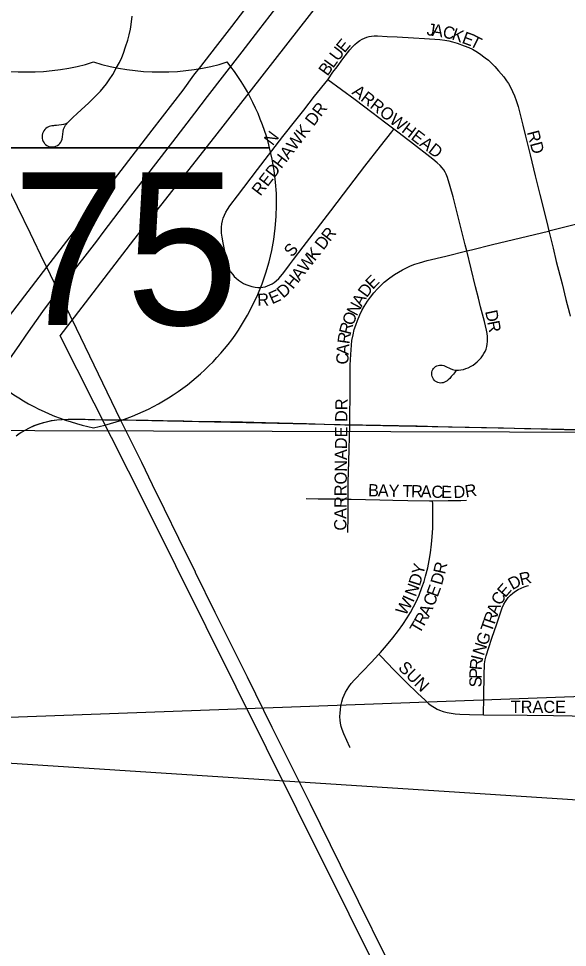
# Model space of a CAD drawing. Extents: x -5.6 to 34, y 0 to 22.
# Drawn here: x 6.458 to 7.358, y 18.084 to 19.608 of the extents above; entities that cross this region are included whole.
import ezdxf

# ---------------------------------------------------------------- set-up
doc = ezdxf.new("R2010")
doc.units = 0
for name, color, linetype in [('GM_X_City_Street', 7, 'Continuous'), ('GM_X_City_Street_Text', 7, 'Continuous'), ('GM_X_Corporation', 7, 'Continuous'), ('GM_X_Interstate_Location', 7, 'Continuous'), ('GM_X_Interstate_Route', 7, 'Continuous'), ('GM_X_Interstate_Shield', 7, 'Continuous'), ('GM_X_Minor_River', 7, 'Continuous'), ('GM_X_Section', 7, 'Continuous'), ('GM_X_State_Route', 7, 'Continuous'), ('GM_X_Township_Road', 7, 'Continuous'), ('GM_X_Township_Subdivision', 7, 'Continuous'), ('GM_X_Township_Subdivision_Text', 7, 'Continuous'), ('SH_Text', 7, 'Continuous')]:
    doc.layers.add(name, color=color, linetype=linetype)

msp = doc.modelspace()

# ---------------------------------------------------------------- linework, layer by layer
at = {"layer": 'GM_X_City_Street'}
for points in [[(6.5359, 19.435), (6.5318, 19.4342), (6.5289, 19.4336), (6.5242, 19.4328), (6.5205, 19.4323), (6.5174, 19.4322), (6.5153, 19.432), (6.5131, 19.4317), (6.5108, 19.4313), (6.5084, 19.4306), (6.5061, 19.4295), (6.505, 19.4289), (6.503, 19.4274), (6.5021, 19.4265), (6.5013, 19.4256), (6.4996, 19.4237), (6.4984, 19.4214), (6.4975, 19.419), (6.497, 19.4164), (6.4968, 19.4138), (6.4971, 19.4112), (6.4978, 19.4087), (6.4987, 19.4062), (6.5, 19.4039), (6.5007, 19.4029), (6.5025, 19.401), (6.5046, 19.3994), (6.5069, 19.3982), (6.5094, 19.3975), (6.512, 19.3971), (6.5146, 19.3971), (6.5172, 19.3976), (6.5196, 19.3984), (6.522, 19.3996), (6.5241, 19.4012), (6.526, 19.403), (6.5276, 19.4051), (6.5288, 19.4074), (6.5297, 19.4098), (6.5305, 19.4137), (6.5313, 19.4228), (6.5315, 19.4241), (6.5317, 19.4254), (6.5321, 19.4265), (6.5335, 19.4297), (6.5341, 19.4308), (6.5354, 19.4329), (6.5361, 19.434), (6.5386, 19.437), (6.5422, 19.4408), (6.5479, 19.4462), (6.5538, 19.4514), (6.5616, 19.4584), (6.573, 19.4692), (6.5852, 19.4812), (6.5924, 19.4888), (6.5976, 19.4947), (6.6025, 19.5009), (6.607, 19.5073), (6.6126, 19.5162), (6.6185, 19.5264), (6.6235, 19.5357), (6.6274, 19.544), (6.6304, 19.5513), (6.6338, 19.5612), (6.6373, 19.5724), (6.6398, 19.5813), (6.6417, 19.5902), (6.6431, 19.598), (6.6448, 19.612)], [(6.9652, 19.5074), (6.9737, 19.5199), (6.9804, 19.5289), (6.9898, 19.5417), (7.0012, 19.5564), (7.0056, 19.5615), (7.0094, 19.5653), (7.0136, 19.5687), (7.018, 19.5718), (7.0215, 19.5739), (7.0252, 19.5758), (7.029, 19.5773), (7.033, 19.5784), (7.0371, 19.5791), (7.0412, 19.5795), (7.0466, 19.5795), (7.0624, 19.5785), (7.0787, 19.5777), (7.1056, 19.5763), (7.124, 19.5752), (7.1489, 19.5733), (7.1569, 19.5723), (7.1634, 19.5711), (7.1699, 19.5695), (7.1775, 19.5672), (7.1887, 19.5632), (7.1962, 19.5602), (7.2022, 19.5574), (7.2081, 19.5541), (7.2137, 19.5505), (7.2234, 19.5436), (7.2286, 19.5394), (7.2335, 19.5349), (7.2391, 19.5292), (7.2453, 19.5222), (7.2536, 19.512), (7.2584, 19.5056), (7.2614, 19.5012), (7.2647, 19.4953), (7.2683, 19.4882), (7.2715, 19.4809), (7.2743, 19.4734), (7.2774, 19.4633), (7.2807, 19.4505), (7.2851, 19.4327), (7.2896, 19.4148), (7.297, 19.3842), (7.3052, 19.3497), (7.3126, 19.3191), (7.32, 19.2912), (7.3259, 19.2669), (7.3277, 19.2594)], [(6.8057, 19.1923), (6.8025, 19.2011), (6.8, 19.2092), (6.7985, 19.2163), (6.7968, 19.2241), (6.7954, 19.2314), (6.7936, 19.2401), (6.792, 19.2493), (6.7912, 19.2559), (6.791, 19.2613), (6.7911, 19.2654), (6.7917, 19.2708), (6.7928, 19.2761), (6.7939, 19.2801), (6.7958, 19.2851), (6.7981, 19.29), (6.8008, 19.2947), (6.8046, 19.3003), (6.8174, 19.317), (6.85, 19.36), (6.8916, 19.4141), (6.9126, 19.4411), (6.9257, 19.4576), (6.9433, 19.4804), (6.9652, 19.5074)], [(7.0737, 19.4261), (7.0602, 19.4364), (7.0372, 19.4538), (7.0099, 19.4743), (6.9652, 19.5074)], [(6.8057, 19.1923), (6.8093, 19.1879), (6.8119, 19.1848), (6.8149, 19.1819), (6.8191, 19.1785), (6.8235, 19.1754), (6.8271, 19.1733), (6.8308, 19.1716), (6.8358, 19.1697), (6.8409, 19.1681), (6.8463, 19.1669), (6.8504, 19.1664), (6.8545, 19.1664), (6.8587, 19.1669), (6.8627, 19.1678), (6.8666, 19.1691), (6.8704, 19.1708), (6.874, 19.1727), (6.8774, 19.175), (6.8807, 19.1774), (6.8847, 19.1811), (6.8883, 19.1851), (6.8933, 19.1913), (6.9027, 19.204), (6.909, 19.2123), (6.9251, 19.2331), (6.9704, 19.2925), (6.9911, 19.3196), (7.0262, 19.3654), (7.0519, 19.3986), (7.0703, 19.4219), (7.0737, 19.4261)], [(7.1931, 19.2266), (7.1906, 19.2367), (7.1791, 19.2825), (7.1705, 19.3155), (7.166, 19.3321), (7.1613, 19.3472), (7.1594, 19.3523), (7.1576, 19.3559), (7.1554, 19.3595), (7.153, 19.3627), (7.1493, 19.3667), (7.1444, 19.3713), (7.1372, 19.3772), (7.1009, 19.4054), (7.0967, 19.4086), (7.08, 19.4213), (7.0737, 19.4261)], [(7.3277, 19.2594), (7.3626, 19.2681), (7.3984, 19.2768), (7.4112, 19.2801), (7.4201, 19.2829), (7.4275, 19.2856), (7.4373, 19.2897), (7.4528, 19.2971), (7.5196, 19.3304)], [(7.1931, 19.2266), (7.2006, 19.2284), (7.235, 19.2372), (7.2925, 19.251), (7.327, 19.2592), (7.3277, 19.2594)], [(7.3277, 19.2594), (7.3345, 19.2312), (7.3397, 19.2095), (7.3492, 19.1726), (7.3556, 19.1471), (7.3613, 19.1242), (7.3624, 19.1193)], [(7.0021, 19.0389), (7.0029, 19.0564), (7.004, 19.072), (7.0049, 19.0798), (7.0066, 19.0887), (7.0087, 19.0975), (7.011, 19.1049), (7.0137, 19.1122), (7.0178, 19.1217), (7.0212, 19.1287), (7.0251, 19.1355), (7.0306, 19.1443), (7.035, 19.1507), (7.0407, 19.1578), (7.0467, 19.1646), (7.0522, 19.1701), (7.0579, 19.1753), (7.0671, 19.1825), (7.0745, 19.1879), (7.0811, 19.192), (7.0879, 19.1957), (7.1008, 19.2019), (7.108, 19.2048), (7.1154, 19.2073), (7.1279, 19.2107), (7.1585, 19.2182), (7.1931, 19.2266)], [(7.1753, 19.0297), (7.1729, 19.0264), (7.1714, 19.0245), (7.1696, 19.0226), (7.1676, 19.0203), (7.1651, 19.0174), (7.1626, 19.015), (7.1609, 19.0134), (7.1589, 19.0121), (7.1568, 19.0111), (7.1546, 19.0103), (7.1523, 19.0099), (7.15, 19.0098), (7.1477, 19.0101), (7.1454, 19.0108), (7.1433, 19.0117), (7.1414, 19.013), (7.1397, 19.0145), (7.1383, 19.0163), (7.1372, 19.0184), (7.1363, 19.0205), (7.1358, 19.0228), (7.1357, 19.0251), (7.1359, 19.0274), (7.1365, 19.0297), (7.1374, 19.0318), (7.1386, 19.0338), (7.1401, 19.0355), (7.1418, 19.0369), (7.1438, 19.038), (7.146, 19.0387), (7.1483, 19.0392), (7.1506, 19.0392), (7.153, 19.039), (7.1553, 19.0385), (7.1587, 19.0372), (7.1659, 19.0337), (7.1697, 19.0322), (7.1738, 19.0312), (7.1766, 19.0309), (7.1794, 19.0309), (7.1836, 19.0313), (7.1876, 19.0321), (7.1915, 19.0334), (7.1953, 19.0349), (7.2002, 19.0373), (7.2037, 19.0394), (7.207, 19.0418), (7.2102, 19.0444), (7.2131, 19.0473), (7.2166, 19.0514), (7.219, 19.0547), (7.2212, 19.0582), (7.2231, 19.0618), (7.2246, 19.0656), (7.2258, 19.0696), (7.2266, 19.0736), (7.2271, 19.0777), (7.2271, 19.0818), (7.2269, 19.0859), (7.2263, 19.0912), (7.2253, 19.0965), (7.2221, 19.1106), (7.2157, 19.1348), (7.2123, 19.1488), (7.2076, 19.1679), (7.2004, 19.1972), (7.1931, 19.2266)], [(7.0016, 18.9415), (7.0015, 18.9435), (7.0015, 18.9593), (7.0018, 18.9856), (7.0017, 19.0105), (7.0021, 19.0381), (7.0021, 19.0389)]]:
    msp.add_lwpolyline(points, dxfattribs=at)
at = {"layer": 'GM_X_Corporation'}
msp.add_lwpolyline([(6.4578, 18.9257), (6.4691, 18.9327), (6.4761, 18.9365), (6.4841, 18.94), (6.4957, 18.9442), (6.5125, 18.9483), (6.5212, 18.9494), (6.5298, 18.9502), (6.545, 18.9507), (6.5992, 18.9496), (6.6256, 18.9497), (6.9854, 18.9417), (7.0015, 18.9415), (7.6222, 18.9287), (7.6355, 18.9285), (7.8251, 18.9258), (7.8363, 18.9257), (8.3062, 18.9202), (7.908, 19.3439), (7.8283, 19.4265), (8.2463, 19.4221), (8.5459, 19.9586)], dxfattribs=at)
at = {"layer": 'GM_X_Interstate_Route'}
for points in [[(6.4434, 19.1203), (6.5045, 19.1998), (6.6774, 19.4249), (6.728, 19.4903), (6.7458, 19.5147), (6.7571, 19.5292), (6.7812, 19.5604), (6.8077, 19.5946), (6.8489, 19.6491), (6.8692, 19.6749), (6.8764, 19.6843), (6.9676, 19.803), (6.9901, 19.832), (7.0116, 19.8603), (7.0636, 19.928), (7.1256, 20.0079), (7.151, 20.0413), (7.1916, 20.0946), (7.2051, 20.1124), (7.2499, 20.1707), (7.2925, 20.2258), (7.3849, 20.342)], [(6.5864, 19.2428), (6.597, 19.2566), (6.6321, 19.3025), (6.6423, 19.3162), (6.7111, 19.4057), (6.7472, 19.4525), (6.7679, 19.4797), (6.8249, 19.5535), (6.8521, 19.5889), (6.9266, 19.6857), (6.9627, 19.7324), (6.9874, 19.7648), (7.0098, 19.794), (7.0433, 19.8378), (7.0866, 19.894), (7.1599, 19.99), (7.2017, 20.0441), (7.2216, 20.0702), (7.2411, 20.0949), (7.2619, 20.122), (7.3092, 20.1834), (7.3458, 20.2314), (7.4003, 20.3021)], [(6.5386, 19.1809), (6.5864, 19.2428)], [(6.5296, 19.1692), (6.5386, 19.1809)], [(6.4602, 19.0733), (6.4705, 19.0885), (6.498, 19.1271), (6.5233, 19.161), (6.524, 19.1619), (6.5296, 19.1692)], [(6.3298, 18.856), (6.3346, 18.8653), (6.3442, 18.8829), (6.3626, 18.9167), (6.3815, 18.9514), (6.4079, 18.9935), (6.4316, 19.0315), (6.4602, 19.0733)]]:
    msp.add_lwpolyline(points, dxfattribs=at)
at = {"layer": 'GM_X_Interstate_Shield'}
for p, q in [((6.2927, 19.3959), (6.8698, 19.3959)), ((6.8698, 19.3959), (6.2927, 19.3959)), ((6.8698, 19.3959), (6.2927, 19.3959))]:
    msp.add_line(p, q, dxfattribs=at)
for centre, start, end in [((6.4717, 19.8952), 253.0091, 286.9909), ((6.6909, 19.8952), 253.0091, 286.9909), ((6.5063, 19.304), 14.1934, 38.331), ((6.6563, 19.304), 165.8066, 258.463), ((6.5063, 19.304), 281.537, 14.1934)]:
    msp.add_arc(centre, 0.375, start, end, dxfattribs=at)
at = {"layer": 'GM_X_Minor_River'}
msp.add_lwpolyline([(8.5297, 15.0523), (8.2755, 15.5636), (7.9273, 16.2717), (7.6894, 16.7524), (7.3893, 17.3541), (7.1716, 17.7937), (6.9143, 18.3107), (6.6663, 18.81), (6.5263, 19.0874), (6.6472, 19.2446), (6.7802, 19.4137), (6.9563, 19.6407), (7.1015, 19.8281), (7.228, 19.9844), (7.2483, 20.0122), (7.2596, 20.0201), (7.2772, 20.0231), (7.3001, 20.0228)], dxfattribs=at)
at = {"layer": 'GM_X_Section'}
for points in [[(7.5006, 20.9), (7.2498, 20.9), (7.2609, 20.8761), (5.343, 19.9706), (5.3166, 18.9352), (7.4578, 18.9294)], [(5.3166, 18.9352), (7.4578, 18.9294), (7.4183, 16.7871), (5.2895, 16.8144)]]:
    msp.add_lwpolyline(points, close=True, dxfattribs=at)
at = {"layer": 'GM_X_State_Route'}
for points in [[(6.5428, 19.1209), (6.524, 19.1595), (6.5233, 19.161), (6.5045, 19.1998), (6.5005, 19.2079), (6.4777, 19.2551), (6.4563, 19.2988), (6.4273, 19.3577), (6.4083, 19.3966), (6.3806, 19.4532), (6.3578, 19.499), (6.3496, 19.5155), (6.3374, 19.5402), (6.3349, 19.5452), (6.3211, 19.5744), (6.3121, 19.5934), (6.3036, 19.6108), (6.2902, 19.6382), (6.2816, 19.6559), (6.2782, 19.6631), (6.2697, 19.681), (6.2598, 19.7018)], [(6.6256, 18.9497), (6.5533, 19.0992), (6.5428, 19.1209)], [(6.7482, 18.6994), (6.7212, 18.7546), (6.6974, 18.8029), (6.678, 18.843), (6.6602, 18.8796), (6.6473, 18.9055), (6.6387, 18.9232), (6.6256, 18.9497)], [(7.1617, 17.8648), (7.1517, 17.8849), (7.1222, 17.945), (7.0612, 18.0672), (7.0158, 18.159), (6.9858, 18.2189), (6.9367, 18.3191), (6.9078, 18.3766), (6.8903, 18.4119), (6.8741, 18.4449), (6.8335, 18.5274), (6.7807, 18.6331), (6.7483, 18.6991), (6.7482, 18.6994)]]:
    msp.add_lwpolyline(points, dxfattribs=at)
at = {"layer": 'GM_X_Township_Road'}
for points in [[(6.4545, 18.9234), (6.4611, 18.9279), (6.4691, 18.9327), (6.4761, 18.9364), (6.4833, 18.9398), (6.4922, 18.943), (6.4993, 18.9453), (6.5057, 18.9469), (6.5132, 18.9484), (6.5212, 18.9494), (6.5291, 18.9502), (6.5398, 18.9507), (6.5517, 18.9508), (6.5676, 18.9504), (6.5834, 18.9499), (6.5992, 18.9496), (6.6256, 18.9497)], [(6.6256, 18.9497), (6.6371, 18.9495), (6.6561, 18.9491), (6.6707, 18.9488), (6.7202, 18.9478), (6.7294, 18.9476), (6.757, 18.9469), (6.7898, 18.9466), (6.8253, 18.9459), (6.8633, 18.9451), (6.9303, 18.9436), (6.9592, 18.9424), (6.9933, 18.9415), (7.0016, 18.9415)], [(7.0016, 18.9415), (7.0025, 18.9415), (7.0223, 18.9415), (7.0813, 18.9404), (7.1115, 18.9396), (7.1456, 18.9385), (7.1693, 18.9381), (7.2533, 18.9361), (7.2875, 18.9352), (7.3151, 18.9346), (7.3321, 18.9342), (7.3741, 18.9333), (7.4214, 18.9322), (7.4661, 18.9315), (7.5173, 18.9302), (7.583, 18.9291), (7.6222, 18.9287)]]:
    msp.add_lwpolyline(points, dxfattribs=at)
at = {"layer": 'GM_X_Township_Subdivision'}
for points in [[(6.9988, 18.8191), (6.9988, 18.8236), (6.9988, 18.8472), (6.9996, 18.8812), (7.0016, 18.9415)], [(6.9297, 18.8201), (6.9494, 18.8197), (6.977, 18.8196), (6.9988, 18.8191)], [(6.998, 18.7647), (6.9986, 18.7909), (6.9988, 18.8191)], [(6.9988, 18.8191), (7.0033, 18.819), (7.0506, 18.8182), (7.0716, 18.8177), (7.0966, 18.8172), (7.1321, 18.8166), (7.1371, 18.8167)], [(7.0489, 18.5648), (7.0514, 18.5675), (7.0617, 18.5793), (7.0717, 18.5915), (7.0814, 18.604), (7.0882, 18.6136), (7.0954, 18.6246), (7.1009, 18.6335), (7.106, 18.6427), (7.1101, 18.651), (7.1148, 18.6618), (7.1195, 18.6741), (7.123, 18.684), (7.1256, 18.6928), (7.129, 18.7068), (7.1314, 18.7184), (7.1336, 18.7314), (7.1354, 18.7457), (7.1365, 18.7575), (7.1373, 18.7719), (7.1376, 18.7876), (7.1374, 18.7987), (7.1372, 18.8117), (7.1371, 18.8167)], [(7.1371, 18.8167), (7.1627, 18.817), (7.1831, 18.8172), (7.1926, 18.8177)], [(7.2205, 18.4652), (7.2205, 18.4676), (7.221, 18.4914), (7.2214, 18.5349), (7.2219, 18.5441), (7.2224, 18.5493), (7.2234, 18.5558), (7.225, 18.5622), (7.2291, 18.5761), (7.234, 18.5911), (7.2421, 18.6148), (7.2512, 18.6409), (7.2538, 18.6469), (7.2564, 18.6516), (7.2586, 18.6548), (7.261, 18.6579), (7.2646, 18.6617), (7.2686, 18.6652), (7.2728, 18.6683), (7.2773, 18.6711), (7.282, 18.6735), (7.2869, 18.6755), (7.2919, 18.677), (7.2945, 18.6776)], [(7.0017, 18.4112), (7.0012, 18.4124), (6.9962, 18.4231), (6.9916, 18.434), (6.9888, 18.4414), (6.9874, 18.4464), (6.9863, 18.4515), (6.9855, 18.4567), (6.9852, 18.462), (6.9853, 18.4685), (6.9858, 18.4738), (6.9868, 18.4803), (6.9882, 18.4867), (6.9901, 18.493), (6.992, 18.4979), (6.9942, 18.5026), (6.9968, 18.5072), (6.9996, 18.5116), (7.0036, 18.5169), (7.0088, 18.5228), (7.0362, 18.5511), (7.0489, 18.5648)], [(7.0489, 18.5648), (7.0527, 18.5609), (7.073, 18.5399), (7.0943, 18.5185), (7.1122, 18.5011), (7.1246, 18.4893), (7.1305, 18.4841), (7.1347, 18.4809), (7.1402, 18.4773), (7.1448, 18.4749), (7.1484, 18.4733), (7.1546, 18.4711), (7.1609, 18.4694), (7.1674, 18.468), (7.1739, 18.4671), (7.1817, 18.4664), (7.1975, 18.4657), (7.2205, 18.4652)], [(7.2205, 18.4652), (7.2211, 18.4652), (7.292, 18.4646), (7.3354, 18.4642), (7.3656, 18.4637), (7.4141, 18.463), (7.4453, 18.463), (7.4876, 18.4622), (7.5151, 18.4617)]]:
    msp.add_lwpolyline(points, dxfattribs=at)
at = {"layer": 'SH_Text'}
msp.add_lwpolyline([(10.6219, 18.1148), (5.6964, 18.4344), (10.6219, 18.6148)], close=True, dxfattribs=at)

# ---------------------------------------------------------------- texts
at = {"layer": 'GM_X_City_Street_Text'}
for s, rotation, p in [('J', 351.6659, (7.1266, 19.5808)), ('A', 351.6811, (7.1353, 19.5796)), ('C', 347.9663, (7.1524, 19.5771)), ('K', 341.0122, (7.1672, 19.574)), ('E', 339.6294, (7.1838, 19.5683)), ('E', 50.7471, (6.9926, 19.5504)), ('T', 333.3739, (7.1964, 19.5636)), ('U', 52.5793, (6.9821, 19.5366)), ('L', 54.1325, (6.9739, 19.5253)), ('B', 54.1066, (6.9646, 19.5124)), ('ARROWHEAD', 322.5077, (7.0035, 19.485)), ('REDHAWK DR', 52.6513, (6.8547, 19.3155)), ('N', 53.1257, (6.8749, 19.3981)), ('RD', 284.7351, (7.2916, 19.4214)), ('R', 52.371, (6.9687, 19.2407)), ('D', 52.3474, (6.958, 19.2268)), ('S', 50.2123, (6.9067, 19.2152)), ('K', 52.3775, (6.944, 19.2086)), ('W', 52.3498, (6.93, 19.1905)), ('H', 51.6524, (6.9082, 19.1626)), ('A', 52.2649, (6.9192, 19.1766)), ('E', 45.4636, (7.0389, 19.1625)), ('E', 23.893, (6.8738, 19.1388)), ('D', 41.5437, (6.8923, 19.1481)), ('D', 53.8907, (7.0291, 19.1489)), ('R', 2.0159, (6.8499, 19.1364)), ('N', 61.9686, (7.0127, 19.1186)), ('A', 61.0982, (7.0209, 19.134)), ('D', 282.0429, (7.223, 19.1274)), ('O', 67.8089, (7.0063, 19.1027)), ('R', 280.6764, (7.2266, 19.1103)), ('R', 75.7459, (7.0026, 19.0881)), ('R', 81.863, (7.0005, 19.073)), ('A', 85.9533, (6.9993, 19.0558)), ('C', 89.3685, (6.9991, 19.0402))]:
    msp.add_text(s, height=0.02, rotation=rotation, dxfattribs=at).set_placement(p)
at = {"layer": 'GM_X_Interstate_Location'}
for s in ['-', '.', ',']:
    msp.add_text(s, height=0.0004, dxfattribs=at).set_placement((6.5812, 19.2363))
msp.add_text('75', height=0.0004, rotation=0, dxfattribs=at).set_placement((6.4995, 19.1535))
at = {"layer": 'GM_X_Interstate_Shield'}
msp.add_text('75', height=0.25, dxfattribs=at).set_placement((6.4477, 19.1053))
at = {"layer": 'GM_X_Township_Subdivision_Text'}
for s, rotation, p in [('CARRONADE DR', 89.4752, (6.9956, 18.7675)), ('B', 358.7129, (7.0311, 18.8241)), ('A', 358.6886, (7.047, 18.8237)), ('Y', 358.7092, (7.0646, 18.8233)), ('T', 358.7128, (7.0874, 18.8228)), ('R', 358.6887, (7.1015, 18.8225)), ('A', 358.7092, (7.1173, 18.8221)), ('C', 358.6887, (7.1349, 18.8217)), ('E', 358.7128, (7.1508, 18.8214)), ('D', 2.8, (7.1717, 18.8209)), ('R', 9.0285, (7.1916, 18.822)), ('Y', 76.3944, (7.1218, 18.6937)), ('R', 76.9547, (7.1573, 18.6951)), ('R', 13.2058, (7.2818, 18.6778)), ('D', 72.3486, (7.116, 18.6755)), ('D', 73.9957, (7.1522, 18.6771)), ('D', 29.1268, (7.2678, 18.6697)), ('N', 69.3323, (7.1094, 18.658)), ('E', 69.5431, (7.1451, 18.6573)), ('E', 48.6342, (7.256, 18.6567)), ('W', 59.2958, (7.0925, 18.6269)), ('I', 65.814, (7.1053, 18.6487)), ('C', 68.8921, (7.1393, 18.6423)), ('C', 61.7946, (7.2492, 18.6437)), ('A', 64.7297, (7.1311, 18.6249)), ('A', 70.8255, (7.2437, 18.6279)), ('R', 61.4327, (7.123, 18.6098)), ('R', 70.828, (7.2385, 18.6129)), ('T', 59.6079, (7.1155, 18.5971)), ('T', 70.842, (7.2339, 18.5996)), ('G', 70.8255, (7.2264, 18.578)), ('N', 71.4752, (7.2208, 18.5613)), ('I', 75.8683, (7.2188, 18.5532)), ('SUN', 315, (7.0794, 18.5414)), ('R', 84.722, (7.2175, 18.5382)), ('P', 89.6994, (7.2174, 18.5246)), ('S', 89.6994, (7.2173, 18.5105)), ('TRACE', 0, (7.2651, 18.4686))]:
    msp.add_text(s, height=0.02, rotation=rotation, dxfattribs=at).set_placement(p)

doc.saveas('drawing.dxf')
